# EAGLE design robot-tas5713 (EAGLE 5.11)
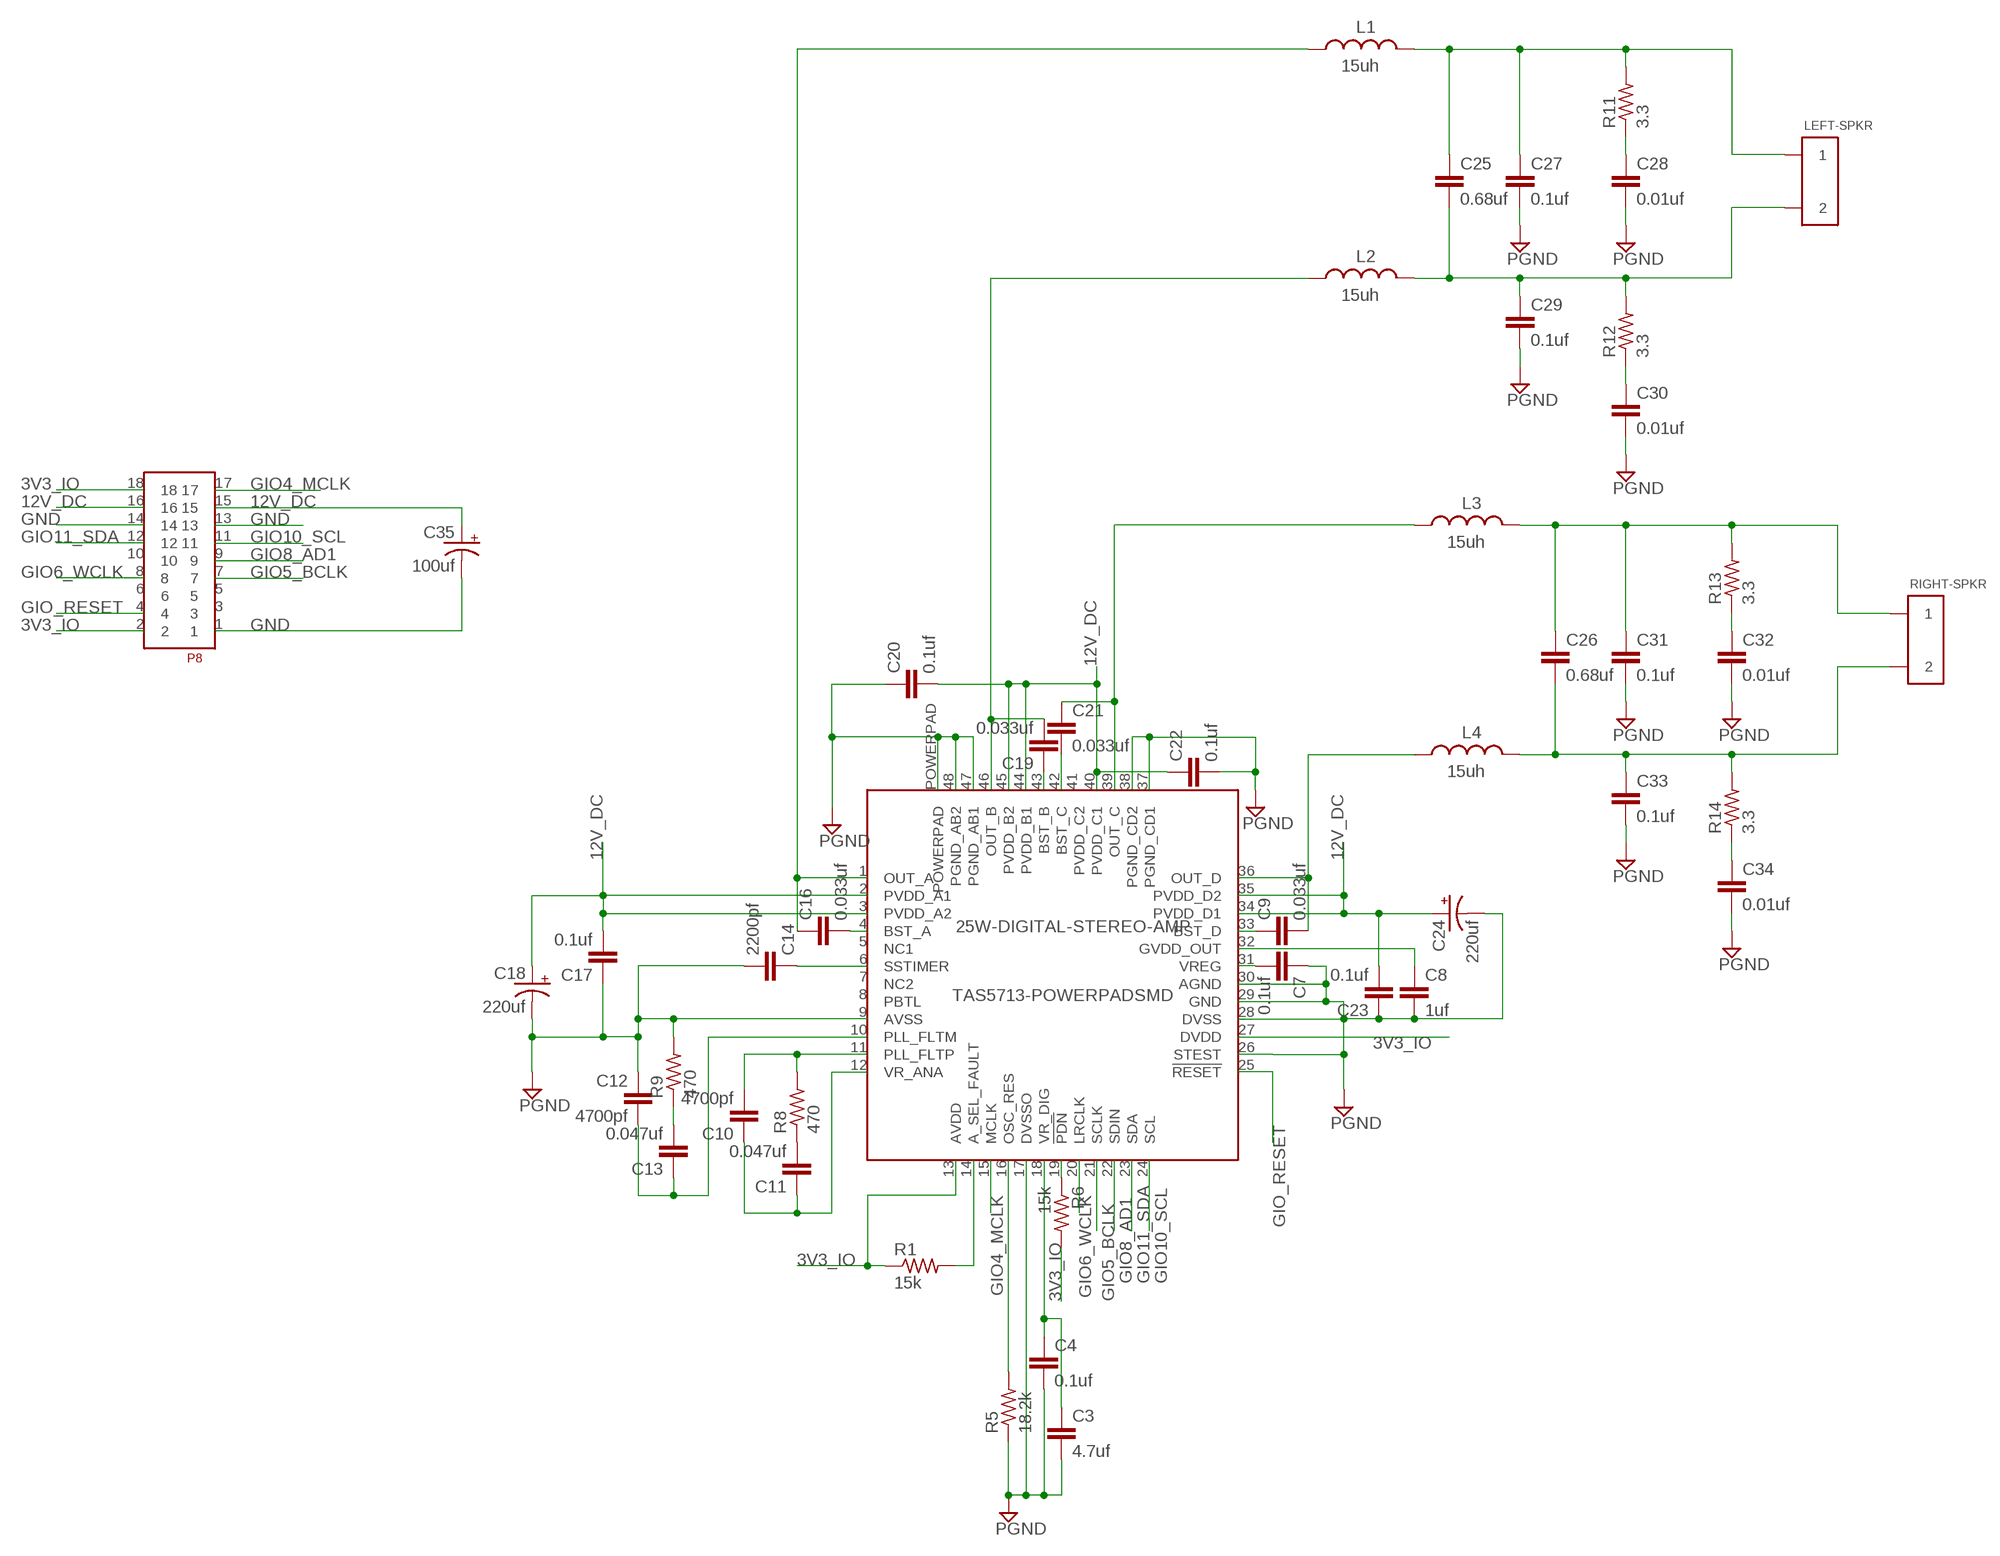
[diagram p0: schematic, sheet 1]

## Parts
25W-DIGITAL-STEREO-AMP  TAS5713-POWERPADSMD  [TQFP-48-POWERPAD]
C3  4.7uf  C-EUC1206  [C1206]
C4  0.1uf  C-EUC1206  [C1206]
C7  0.1uf  C-EUC1206  [C1206]
C8  1uf  C-EUC1206  [C1206]
C9  0.033uf  C-EUC1206  [C1206]
C10  4700pf  C-EUC1206  [C1206]
C11  0.047uf  C-EUC1206  [C1206]
C12  4700pf  C-EUC1206  [C1206]
C13  0.047uf  C-EUC1206  [C1206]
C14  2200pf  C-EUC1206  [C1206]
C16  0.033uf  C-EUC1206  [C1206]
C17  0.1uf  C-EUC1206  [C1206]
C18  220uf  CPOL-US175TMP-0808  [175TMP-0808]
C19  0.033uf  C-EUC1206  [C1206]
C20  0.1uf  C-EUC1206  [C1206]
C21  0.033uf  C-EUC1206  [C1206]
C22  0.1uf  C-EUC1206  [C1206]
C23  0.1uf  C-EUC1206  [C1206]
C24  220uf  CPOL-US175TMP-0808  [175TMP-0808]
C25  0.68uf  C-EUC1206  [C1206]
C26  0.68uf  C-EUC1206  [C1206]
C27  0.1uf  C-EUC1206  [C1206]
C28  0.01uf  C-EUC1206  [C1206]
C29  0.1uf  C-EUC1206  [C1206]
C30  0.01uf  C-EUC1206  [C1206]
C31  0.1uf  C-EUC1206  [C1206]
C32  0.01uf  C-EUC1206  [C1206]
C33  0.1uf  C-EUC1206  [C1206]
C34  0.01uf  C-EUC1206  [C1206]
C35  100uf  CPOL-US175TMP-0808  [175TMP-0808]
L1  15uh  INDUCTOR-ABRACON-1306S  [INDUCTOR-ABRACON-1306S]
L2  15uh  INDUCTOR-ABRACON-1306S  [INDUCTOR-ABRACON-1306S]
L3  15uh  INDUCTOR-ABRACON-1306S  [INDUCTOR-ABRACON-1306S]
L4  15uh  INDUCTOR-ABRACON-1306S  [INDUCTOR-ABRACON-1306S]
LEFT-SPKR  SCREW-CLAMP-2909  [SCREW-CLAMP-909]
P8  HEADER-2X9  [HEADER-2X9]
R1  15k  R-US_R1206  [R1206]
R5  18.2k  R-US_R1206  [R1206]
R6  15k  R-US_R1206  [R1206]
R8  470  R-US_R1206  [R1206]
R9  470  R-US_R1206  [R1206]
R11  3.3  R-US_R1206  [R1206]
R12  3.3  R-US_R1206  [R1206]
R13  3.3  R-US_R1206  [R1206]
R14  3.3  R-US_R1206  [R1206]
RIGHT-SPKR  SCREW-CLAMP-2909  [SCREW-CLAMP-909]

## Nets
3V3_IO: 25W-DIGITAL-STEREO-AMP.13(AVDD) 25W-DIGITAL-STEREO-AMP.27(DVDD) P8.2 P8.18 R1.1 R6.2
12V_DC: 25W-DIGITAL-STEREO-AMP.2(PVDD_A1) 25W-DIGITAL-STEREO-AMP.3(PVDD_A2) 25W-DIGITAL-STEREO-AMP.34(PVDD_D1) 25W-DIGITAL-STEREO-AMP.35(PVDD_D2) 25W-DIGITAL-STEREO-AMP.40(PVDD_C1) 25W-DIGITAL-STEREO-AMP.44(PVDD_B1) 25W-DIGITAL-STEREO-AMP.45(PVDD_B2) C17.2 C18.+ C20.2 C22.1 C23.2 C24.+ C35.+ P8.15 P8.16
GIO4_MCLK: 25W-DIGITAL-STEREO-AMP.15(MCLK) P8.17
GIO5_BCLK: 25W-DIGITAL-STEREO-AMP.21(SCLK) P8.7
GIO6_WCLK: 25W-DIGITAL-STEREO-AMP.20(LRCLK) P8.8
GIO8_AD1: 25W-DIGITAL-STEREO-AMP.22(SDIN) P8.9
GIO10_SCL: 25W-DIGITAL-STEREO-AMP.24(SCL) P8.11
GIO11_SDA: 25W-DIGITAL-STEREO-AMP.23(SDA) P8.12
GIO_RESET: 25W-DIGITAL-STEREO-AMP.25(!RESET) P8.4
GND: 25W-DIGITAL-STEREO-AMP.9(AVSS) 25W-DIGITAL-STEREO-AMP.17(DVSSO) 25W-DIGITAL-STEREO-AMP.26(STEST) 25W-DIGITAL-STEREO-AMP.28(DVSS) 25W-DIGITAL-STEREO-AMP.29(GND) 25W-DIGITAL-STEREO-AMP.30(AGND) 25W-DIGITAL-STEREO-AMP.37(PGND_CD1) 25W-DIGITAL-STEREO-AMP.38(PGND_CD2) 25W-DIGITAL-STEREO-AMP.47(PGND_AB1) 25W-DIGITAL-STEREO-AMP.48(PGND_AB2) 25W-DIGITAL-STEREO-AMP.POWERPAD C3.2 C4.2 C7.1 C8.2 C12.1 C14.2 C17.1 C18.- C20.1 C22.2 C23.1 C24.- C27.2 C28.2 C29.2 C30.2 C31.2 C32.2 C33.2 C34.2 C35.- P8.1 P8.13 P8.14 R5.1 R9.2 ; supply symbol labelled PGND
N$1: 25W-DIGITAL-STEREO-AMP.4(BST_A) C16.2
N$2: 25W-DIGITAL-STEREO-AMP.1(OUT_A) C16.1 L1.1
N$3: 25W-DIGITAL-STEREO-AMP.43(BST_B) C19.1
N$4: 25W-DIGITAL-STEREO-AMP.46(OUT_B) C19.2 L2.1
N$5: 25W-DIGITAL-STEREO-AMP.42(BST_C) C21.2
N$6: 25W-DIGITAL-STEREO-AMP.14(A_SEL_FAULT) R1.2
N$7: 25W-DIGITAL-STEREO-AMP.33(BST_D) C9.1
N$8: 25W-DIGITAL-STEREO-AMP.36(OUT_D) C9.2 L4.1
N$9: 25W-DIGITAL-STEREO-AMP.31(VREG) C7.2
N$10: 25W-DIGITAL-STEREO-AMP.32(GVDD_OUT) C8.1
N$11: 25W-DIGITAL-STEREO-AMP.6(SSTIMER) C14.1
N$12: C28.1 R11.1
N$13: C25.2 C29.1 L2.2 LEFT-SPKR.2 R12.2
N$14: C30.1 R12.1
N$15: 25W-DIGITAL-STEREO-AMP.39(OUT_C) C21.1 L3.1
N$16: 25W-DIGITAL-STEREO-AMP.18(VR_DIG) C3.1 C4.1
N$17: 25W-DIGITAL-STEREO-AMP.16(OSC_RES) R5.2
N$18: C26.1 C31.1 L3.2 R13.2 RIGHT-SPKR.1
N$19: C25.1 C27.1 L1.2 LEFT-SPKR.1 R11.2
N$20: C32.1 R13.1
N$21: C26.2 C33.1 L4.2 R14.2 RIGHT-SPKR.2
N$22: C34.1 R14.1
N$23: 25W-DIGITAL-STEREO-AMP.19(!PDN) R6.1
N$24: 25W-DIGITAL-STEREO-AMP.10(PLL_FLTM) C12.2 C13.1
N$25: 25W-DIGITAL-STEREO-AMP.11(PLL_FLTP) C10.2 R8.2
N$26: 25W-DIGITAL-STEREO-AMP.12(VR_ANA) C10.1 C11.1
N$27: C11.2 R8.1
N$28: C13.2 R9.1
Unconnected: 25W-DIGITAL-STEREO-AMP.5(NC1) 25W-DIGITAL-STEREO-AMP.7(NC2) 25W-DIGITAL-STEREO-AMP.8(PBTL) 25W-DIGITAL-STEREO-AMP.41(PVDD_C2) P8.3 P8.5 P8.6 P8.10

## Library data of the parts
25W-DIGITAL-STEREO-AMP = trl:TAS5713-POWERPAD
C3 C4 C7-C14 C16 C17 C19-C23 C25-C34 = rcl:C-EU: CAPACITOR, European symbol
C18 C24 C35 = resistor:CPOL-US: POLARIZED CAPACITOR, American symbol
L1-L4 = trl:INDUCTOR-ABRACON-1306S
LEFT-SPKR RIGHT-SPKR = trl:SCREW-CLAMP-2
P8 = trl:HEADER-2X9
R1 R5 R6 R8 R9 R11-R14 = resistor:R-US_: RESISTOR, American symbol

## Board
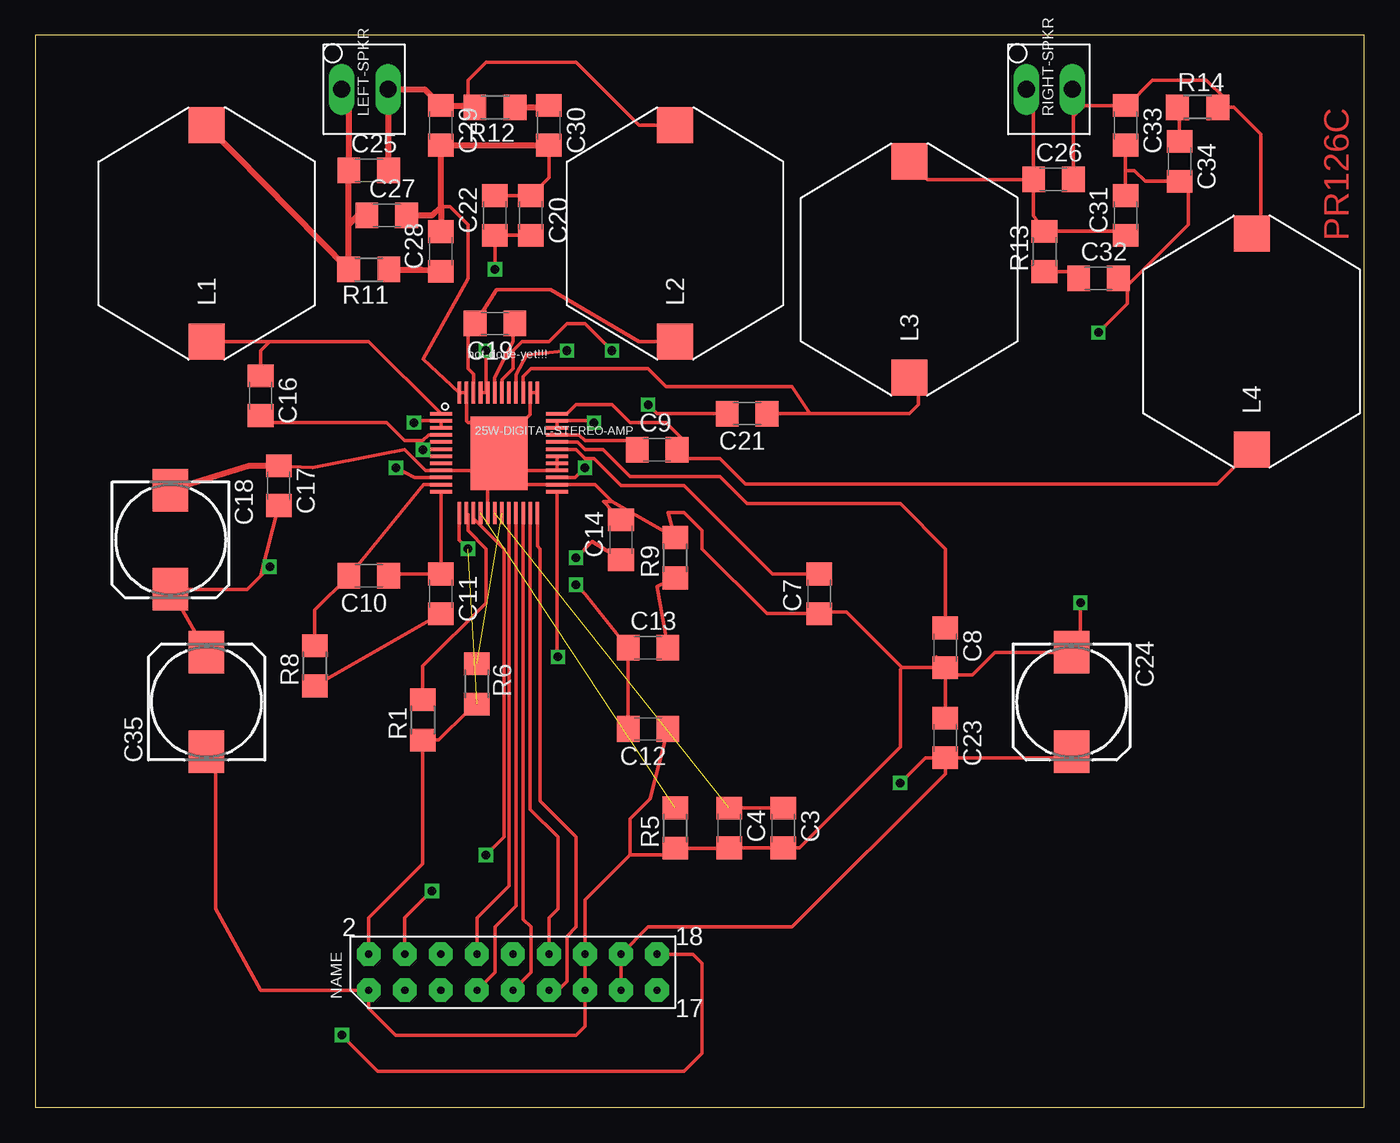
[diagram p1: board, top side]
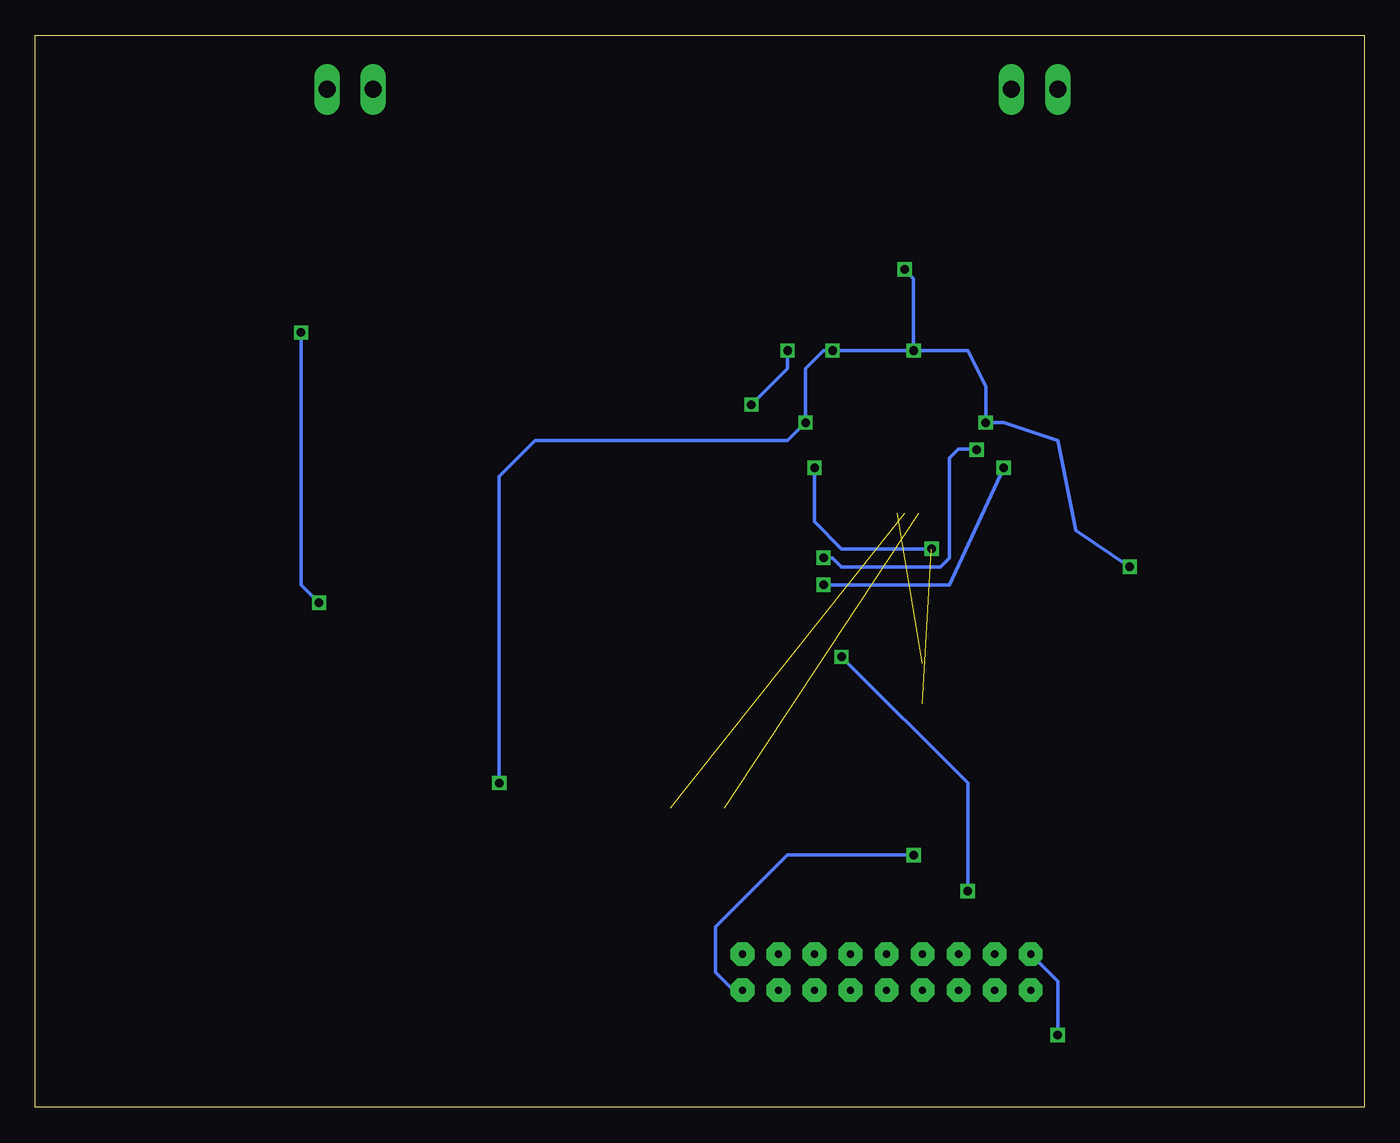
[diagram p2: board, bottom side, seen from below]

Size 93.65 x 75.56 mm. Coordinates in mm from the lower left corner, seen from the top.
Outline: 0,0 93.65,0 93.65,75.56 0,75.56 0,0
Copper layers (1*16): Top 0.035mm / dielectric 1.5mm / Bottom 0.035mm
Design rules "default": minimum track width 10mil, minimum drill 24mil, track to track 8mil, track to pad 8mil, pad to pad 8mil, via to via 8mil, smd to smd 8mil, copper to edge 40mil, drill to drill 8mil, minimum pad ring 10mil, minimum via ring 8mil, stop-mask expansion 4mil, vias tented up to drill 0mil, thermal gap 10mil

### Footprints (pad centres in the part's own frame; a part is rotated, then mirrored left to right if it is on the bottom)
TQFP-48-POWERPAD = smd 1.55 x 0.25: 1 -3.81,2.54; 2 -3.81,2.04; 3 -3.81,1.54; 4 -3.81,1.04; 5 -3.81,0.54; 6 -3.81,0.04; 7 -3.81,-0.46; 8 -3.81,-0.96; 9 -3.81,-1.46; 10 -3.81,-1.96; 11 -3.81,-2.46; 12 -3.81,-2.96; 25 4.39,-2.96; 26 4.39,-2.46; 27 4.39,-1.96; 28 4.39,-1.46; 29 4.39,-0.96; 30 4.39,-0.46; 31 4.39,0.04; 32 4.39,0.54; 33 4.39,1.04; 34 4.39,1.54; 35 4.39,2.04; 36 4.39,2.54 | smd 0.25 x 1.55: 13 -2.51,-4.46; 14 -2.01,-4.46; 15 -1.51,-4.46; 16 -1.01,-4.46; 17 -0.51,-4.46; 18 -0.01,-4.46; 19 0.49,-4.46; 20 0.99,-4.46; 21 1.49,-4.46; 22 1.99,-4.46; 23 2.49,-4.46; 24 2.99,-4.46; 37 2.99,4.04; 38 2.49,4.04; 39 1.99,4.04; 40 1.49,4.04; 41 0.99,4.04; 42 0.49,4.04; 43 -0.01,4.04; 44 -0.51,4.04; 45 -1.01,4.04; 46 -1.51,4.04; 47 -2.01,4.04; 48 -2.51,4.04 | smd 4.04 x 5.17: POWERPAD 0.29,-0.26
C1206 = smd 1.6 x 1.8: 1 -1.4,0; 2 1.4,0
175TMP-0808 = smd 3 x 2.5: + 3.5,0; - -3.5,0
INDUCTOR-ABRACON-1306S = smd 2.54 x 2.54: 1 0,0; 2 15.24,0
SCREW-CLAMP-909 = drill 1.2 long: 1 0,0; 2 3.251,0
HEADER-2X9 = drill 0.5 pad 1.676 octagon: 1 -11.43,-1.27; 2 -11.43,1.27; 3 -8.89,-1.27; 4 -8.89,1.27; 5 -6.35,-1.27; 6 -6.35,1.27; 7 -3.81,-1.27; 8 -3.81,1.27; 9 -1.27,-1.27; 10 -1.27,1.27; 11 1.27,-1.27; 12 1.27,1.27; 13 3.81,-1.27; 14 3.81,1.27; 15 6.35,-1.27; 16 6.35,1.27; 17 8.89,-1.27; 18 8.89,1.27
R1206 = smd 1.6 x 1.803: 1 -1.422,0; 2 1.422,0

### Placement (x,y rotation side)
25W-DIGITAL-STEREO-AMP  32.38,46.35 0 top
C3  52.7,19.68 270 top
C4  48.9,19.68 270 top
C7  55.24,36.2 90 top
C8  64.14,32.38 270 top
C9  43.81,46.35 0 top
C10  23.5,37.47 180 top
C11  28.57,36.2 270 top
C12  43.18,26.67 180 top
C13  43.18,32.38 0 top
C14  41.27,40.01 90 top
C16  15.88,50.16 270 top
C17  17.14,43.81 270 top
C18  9.53,40.01 270 top
C19  32.38,55.24 180 top
C20  34.92,62.87 270 top
C21  50.16,48.9 180 top
C22  32.38,62.87 90 top
C23  64.14,26.04 270 top
C24  73.03,28.57 270 top
C25  23.5,66.04 0 top
C26  71.75,65.41 0 top
C27  24.77,62.87 0 top
C28  28.57,60.33 90 top
C29  28.57,69.22 270 top
C30  36.2,69.22 270 top
C31  76.83,62.87 90 top
C32  74.93,58.42 0 top
C33  76.83,69.22 270 top
C34  80.64,66.67 270 top
C35  12.06,28.57 90 top
L1  12.06,53.98 90 top
L2  45.09,53.98 90 top
L3  61.59,51.44 90 top
L4  85.72,46.35 90 top
LEFT-SPKR  21.59,71.75 0 top
P8  34.92,9.53 0 top
R1  27.3,27.3 90 top
R5  45.09,19.68 90 top
R6  31.11,29.84 270 top
R8  19.68,31.11 90 top
R9  45.09,38.73 90 top
R11  23.5,59.05 180 top
R12  32.38,70.48 180 top
R13  71.12,60.33 90 top
R14  81.92,70.48 0 top
RIGHT-SPKR  69.85,71.75 0 top

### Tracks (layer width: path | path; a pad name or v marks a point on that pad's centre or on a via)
3V3_IO  (via drill 0.6)  (1 unrouted)
  Top 0.254: P8.2 23.5,13.34 27.3,17.14 R1.1 28.42,25.88 30.48,27.94 30.63,27.94 R6.2 | 25W-DIGITAL-STEREO-AMP.13 29.88,39.98 v30.48,39.37 | 25W-DIGITAL-STEREO-AMP.27 38.05,44.4 v38.73,45.09 | P8.18 46.35,10.79 46.99,10.16 46.99,3.81 45.72,2.54 24.13,2.54 v21.59,5.08
  Bottom 0.254: v30.48,39.37 36.83,39.37 38.73,41.27 v38.73,45.09 | v21.59,5.08 21.59,8.89 P8.2
12V_DC  (via drill 0.6)
  Top 0.254: 25W-DIGITAL-STEREO-AMP.3 25W-DIGITAL-STEREO-AMP.2 26.8,48.4 v26.67,48.26 | C20.2 C22.1 v32.38,59.05 | 25W-DIGITAL-STEREO-AMP.45 25W-DIGITAL-STEREO-AMP.44 31.75,50.52 v31.75,53.34 | 15.88,37.47 v16.51,38.1 | 15.88,37.47 C17.2 | C35.+ C18.+ 14.91,36.51 15.88,37.47 | C23.2 72.58,24.64 C24.+ | 25W-DIGITAL-STEREO-AMP.40 33.88,51.66 34.61,53.02 v37.47,53.34 | 25W-DIGITAL-STEREO-AMP.34 25W-DIGITAL-STEREO-AMP.35 39.23,48.4 v39.37,48.26 | C23.2 64.14,23.5 53.34,12.7 43.18,12.7 P8.16 P8.15 | C23.2 62.73,24.64 v60.96,22.86
  Bottom 0.254: v31.75,53.34 27.94,53.34 26.67,50.8 v26.67,48.26 25.4,48.26 21.59,46.99 20.32,40.64 v16.51,38.1 | v31.75,53.34 31.75,58.42 v32.38,59.05 | v31.75,53.34 v37.47,53.34 38.1,53.34 39.37,52.07 v39.37,48.26 40.64,46.99 58.42,46.99 60.96,44.45 v60.96,22.86
GIO4_MCLK  (via drill 0.6)
  Top 0.254: 25W-DIGITAL-STEREO-AMP.15 30.88,41.52 33.02,39.37 33.02,19.05 v31.75,17.78
  Bottom 0.254: v31.75,17.78 40.64,17.78 45.72,12.7 45.72,9.53 44.77,8.57 44.45,8.26 P8.17
GIO5_BCLK
  Top 0.254: 25W-DIGITAL-STEREO-AMP.21 33.88,14.19 32.38,12.7 32.38,9.53 P8.7
GIO6_WCLK
  Top 0.254: P8.8 31.11,13.34 33.38,15.6 25W-DIGITAL-STEREO-AMP.20
GIO8_AD1
  Top 0.254: 25W-DIGITAL-STEREO-AMP.22 34.38,13.25 34.92,12.7 34.92,9.53 P8.9
GIO10_SCL
  Top 0.254: 25W-DIGITAL-STEREO-AMP.24 35.38,39.55 35.56,39.37 35.56,21.59 38.1,19.05 38.1,12.7 37.47,12.06 37.47,8.89 36.83,8.26 P8.11
GIO11_SDA
  Top 0.254: P8.12 36.2,13.34 36.83,13.97 36.83,19.05 34.88,21 25W-DIGITAL-STEREO-AMP.23
GIO_RESET  (via drill 0.6)
  Top 0.254: P8.4 26.04,13.34 v27.94,15.24 | 25W-DIGITAL-STEREO-AMP.25 36.77,31.8 v36.83,31.75
  Bottom 0.254: v36.83,31.75 27.94,22.86 v27.94,15.24
GND  (via drill 0.6)
  Top 0.254: 76.83,66.04 C31.2 | 76.83,66.04 C33.2 | 76.97,57.91 C32.2 | 76.97,57.91 81.28,62.23 81.28,64.64 C34.2 78.23,65.28 77.47,66.04 76.83,66.04 | C30.2 36.2,65.53 C20.1 C22.2 | 28.57,63.5 29.21,63.5 30.48,62.23 30.48,58.42 27.34,52.73 25W-DIGITAL-STEREO-AMP.48 25W-DIGITAL-STEREO-AMP.47 30.38,48.37 30.48,48.26 31.48,48.26 | 31.48,44.9 25W-DIGITAL-STEREO-AMP.9 27.5,44.9 26.04,46.35 19.55,45.09 C17.1 | 25W-DIGITAL-STEREO-AMP.POWERPAD 31.48,44.9 | 31.48,44.9 31.48,48.26 | 31.48,48.26 31.48,48.53 | 25W-DIGITAL-STEREO-AMP.17 31.88,44.49 31.48,44.9 | 25W-DIGITAL-STEREO-AMP.POWERPAD 32.88,45.9 | 33.02,44.45 33.58,43.9 25W-DIGITAL-STEREO-AMP.26 39.44,43.9 40.64,42.7 | 33.02,45.72 33.02,45.75 25W-DIGITAL-STEREO-AMP.POWERPAD | 33.02,44.45 33.02,45.72 | 32.58,44.9 31.75,45.72 31.75,46.99 33.02,45.72 | 25W-DIGITAL-STEREO-AMP.30 25W-DIGITAL-STEREO-AMP.29 25W-DIGITAL-STEREO-AMP.28 33.47,44.9 33.02,44.45 | 25W-DIGITAL-STEREO-AMP.37 25W-DIGITAL-STEREO-AMP.38 34.88,48.84 34.29,48.26 34.29,47.71 25W-DIGITAL-STEREO-AMP.POWERPAD | C35.- 12.7,24.44 12.7,13.97 15.88,8.26 P8.1 23.5,6.99 25.4,5.08 38.1,5.08 38.73,5.71 P8.13 P8.14 38.73,14.61 41.91,17.78 | 41.91,17.78 44.6,17.78 R5.1 48.87,18.26 C4.2 C3.2 53.84,18.29 60.96,25.4 60.96,30.86 61.09,30.98 | C8.2 64.64,30.48 66.04,30.48 67.64,32.08 C24.- 73.66,32.71 v73.66,35.56 | C8.2 C23.1 64.14,31.11 63.5,31.75 | 76.97,57.91 76.97,56.65 v74.93,54.61 | 40.64,42.7 40.03,42.7 C14.2 | 40.64,42.7 R9.2 44.6,41.91 45.72,41.91 46.99,40.64 46.99,39.37 51.56,34.8 C7.1 55.38,34.92 57.15,34.92 61.09,30.98 | 61.09,30.98 C8.2 | C12.1 43.31,21.72 41.91,20.32 41.91,17.78
  Top 0.406: C30.2 C29.2 28.57,63.5 | 28.57,63.5 C28.2 | C27.2 27.94,62.87 28.57,63.5 | C17.1 15.04,45.22 C18.-
  Bottom 0.254: v74.93,54.61 74.93,36.83 v73.66,35.56
N$1
  Top 0.254: 25W-DIGITAL-STEREO-AMP.4 27.71,47.4 27.3,46.99 26.04,46.99 24.77,48.26 16.38,48.26 C16.2
N$2
  Top 0.254: 25W-DIGITAL-STEREO-AMP.1 23.5,53.98 16.51,53.98 | L1.1 16.51,53.98 | C16.1 15.88,53.34 16.51,53.98
N$3
  Top 0.254: 25W-DIGITAL-STEREO-AMP.43 32.38,51.42 33.66,53.98 33.66,55.12 C19.1
N$4
  Top 0.254: L2.1 42.55,53.98 36.33,57.66 32.52,57.66 C19.2 30.48,54.74 30.48,52.07 30.88,51.67 25W-DIGITAL-STEREO-AMP.46
N$5  (via drill 0.6)
  Top 0.254: C21.2 43.81,48.9 v43.18,49.53 | 25W-DIGITAL-STEREO-AMP.42 32.88,51.29 33.66,52.07 33.66,53.34 34.29,53.98 36.2,53.98 37.47,55.24 38.73,55.24 v40.64,53.34
  Bottom 0.254: v40.64,53.34 40.64,52.07 v43.18,49.53
N$6
  Top 0.254: R1.2 27.3,31.11 31.75,35.56 31.75,39.37 30.48,40.64 30.48,41.79 25W-DIGITAL-STEREO-AMP.14
N$7
  Top 0.254: 25W-DIGITAL-STEREO-AMP.33 38.33,47.4 38.73,46.99 41.78,46.99 C9.1
N$8
  Top 0.254: L4.1 83.31,43.95 50.03,43.95 48.26,45.72 45.85,45.72 C9.2 45.72,46.86 45.72,46.99 44.45,48.26 41.91,48.26 40.64,49.53 38.1,49.53 37.47,48.9 25W-DIGITAL-STEREO-AMP.36
N$9
  Top 0.254: C7.2 51.94,37.59 45.72,43.81 41.27,43.81 39.37,45.72 38.73,45.72 38.1,46.35 36.81,46.35 25W-DIGITAL-STEREO-AMP.31
N$10
  Top 0.254: 25W-DIGITAL-STEREO-AMP.32 38.2,46.9 38.73,46.35 40.01,46.35 41.91,44.45 48.26,44.45 50.16,42.55 60.96,42.55 64.14,39.37 C8.1
N$11  (via drill 0.6)
  Top 0.254: C14.1 39.24,39.88 v38.1,38.73 | v27.3,46.35 28.54,46.35 25W-DIGITAL-STEREO-AMP.6
  Bottom 0.254: v38.1,38.73 37.47,38.73 36.83,38.1 29.84,38.1 29.21,38.73 29.21,45.76 25W-DIGITAL-STEREO-AMP.6 27.34,46.4 v27.3,46.35
N$12
  Top 0.406: R11.1 27.18,59.05 C28.1
N$13
  Top 0.254: L2.2 42.55,69.22 38.1,73.66 31.75,73.66 30.48,72.39 30.48,70.61
  Top 0.406: R12.2 30.83,70.61 30.48,70.61 C29.1 27.43,71.75 LEFT-SPKR.2 24.89,71.7 C25.2
N$14
  Top 0.406: R12.1 36.06,70.48 C30.1
N$15
  Top 0.254: 60.96,52.07 L3.1 62.23,50.8 62.23,49.53 61.59,48.9 54.61,48.9 | 25W-DIGITAL-STEREO-AMP.39 34.38,51.52 34.92,52.07 43.18,52.07 44.45,50.8 53.34,50.8 54.61,48.9 | 54.61,48.9 C21.1
N$16  (1 unrouted)
  Top 0.254: C4.1 C3.1
N$17  (1 unrouted)
N$18
  Top 0.254: C26.1 70.36,71.25 RIGHT-SPKR.1 | C26.1 62.87,65.41 L3.2 | C26.1 70.36,62.84 R13.2 76.55,61.75 C31.1
N$19
  Top 0.406: LEFT-SPKR.1 22.09,71.25 C25.1 22.07,66.02 22.07,62.23 | L1.2 R11.2 22.07,62.23 | C27.1 22.71,62.87 22.07,62.23
N$20
  Top 0.254: R13.1 73.05,58.9 C32.1
N$21
  Top 0.254: C26.2 73.16,69.85 | 73.16,69.85 73.16,71.7 RIGHT-SPKR.2 | 73.16,69.85 73.92,70.61 C33.1 76.97,70.61 78.74,72.39 82.55,72.39 83.82,71.12 83.82,70.97 R14.2 84.45,70.48 86.36,68.58 86.36,62.23 L4.2
N$22
  Top 0.254: C34.1 80.64,70.33 R14.1
N$23  (1 unrouted)
N$24  (via drill 0.6)
  Top 0.254: v38.1,36.83 38.73,36.2 C13.1 C12.2 | 25W-DIGITAL-STEREO-AMP.10 26.73,44.4 v25.4,45.09
  Bottom 0.254: v38.1,36.83 29.21,36.83 v25.4,45.09
N$25
  Top 0.254: 25W-DIGITAL-STEREO-AMP.11 27.36,43.9 C10.2 19.68,35.05 R8.2
N$26
  Top 0.254: 28.16,43.4 25W-DIGITAL-STEREO-AMP.12 C11.1 25.02,37.59 C10.1
N$27
  Top 0.254: R8.1 28.55,34.77 C11.2
N$28
  Top 0.254: R9.1 43.81,36.7 C13.2

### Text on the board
Top: PR126C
